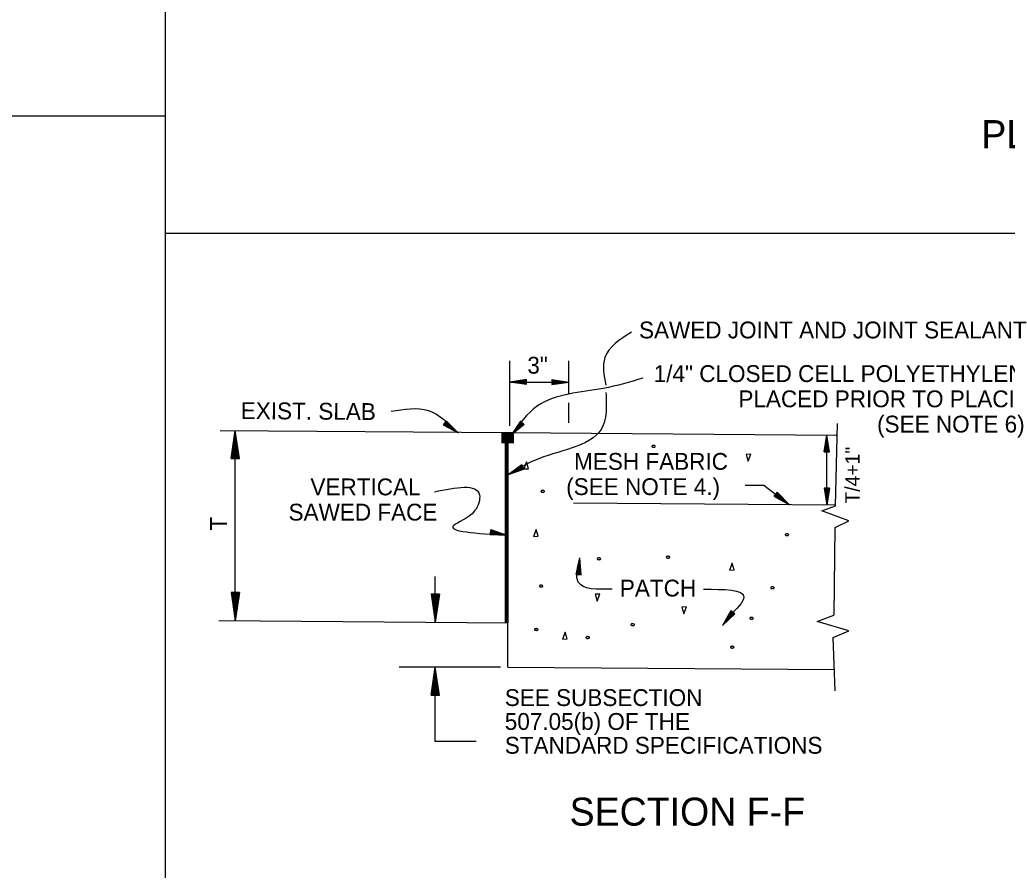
# Model space of a CAD drawing. Extents: x 1375738 to 1375905, y 380661 to 380875.
# Drawn here: x 1375781.94 to 1375810.09, y 380793.26 to 380817.52 of the extents above; entities that cross this region are included whole.
import ezdxf

# ---------------------------------------------------------------- set-up
doc = ezdxf.new("R2010")
doc.units = 0
doc.layers.add('R_Border', color=7, linetype='Continuous')
doc.layers.add('R_Draft', color=7, linetype='Continuous')

msp = doc.modelspace()

# ---------------------------------------------------------------- linework, layer by layer
at = {"layer": 'R_Border'}
for p, q in [((1375786.095, 380770.053), (1375786.095, 380850.32)), ((1375744.419, 380814.777), (1375786.095, 380814.777)), ((1375786.095, 380811.429), (1375854.78, 380811.429))]:
    msp.add_line(p, q, dxfattribs=at)
at = {"layer": 'R_Draft'}
for p, q in [((1375795.908, 380805.938), (1375795.908, 380807.788)), ((1375797.589, 380806.848), (1375797.589, 380807.788)), ((1375796.388, 380807.258), (1375795.908, 380807.186)), ((1375796.388, 380807.246), (1375795.988, 380807.186)), ((1375796.388, 380807.234), (1375796.071, 380807.186)), ((1375796.388, 380807.222), (1375796.151, 380807.186)), ((1375796.388, 380807.21), (1375796.232, 380807.186)), ((1375796.388, 380807.197), (1375796.312, 380807.186)), ((1375796.388, 380807.114), (1375796.388, 380807.258)), ((1375797.109, 380807.258), (1375797.589, 380807.186)), ((1375797.109, 380807.258), (1375797.109, 380807.114)), ((1375797.109, 380807.246), (1375797.509, 380807.186)), ((1375797.109, 380807.234), (1375797.426, 380807.186)), ((1375797.109, 380807.222), (1375797.346, 380807.186)), ((1375797.109, 380807.209), (1375797.265, 380807.186)), ((1375797.109, 380807.197), (1375797.185, 380807.186)), ((1375795.908, 380807.186), (1375797.589, 380807.186)), ((1375796.388, 380807.114), (1375795.908, 380807.186)), ((1375796.388, 380807.126), (1375795.988, 380807.186)), ((1375796.388, 380807.139), (1375796.071, 380807.186)), ((1375796.388, 380807.151), (1375796.151, 380807.186)), ((1375796.388, 380807.163), (1375796.232, 380807.186)), ((1375796.388, 380807.175), (1375796.312, 380807.186)), ((1375797.109, 380807.114), (1375797.589, 380807.186)), ((1375797.109, 380807.163), (1375797.265, 380807.186)), ((1375797.109, 380807.139), (1375797.426, 380807.186)), ((1375797.109, 380807.126), (1375797.509, 380807.186)), ((1375797.109, 380807.151), (1375797.346, 380807.186)), ((1375797.109, 380807.175), (1375797.185, 380807.186)), ((1375797.589, 380806.025), (1375797.589, 380806.597)), ((1375794.096, 380806.082), (1375794.008, 380805.967)), ((1375794.081, 380806.062), (1375794.305, 380805.833)), ((1375794.088, 380806.072), (1375794.37, 380805.783)), ((1375794.096, 380806.082), (1375794.434, 380805.734)), ((1375796.213, 380806.074), (1375795.945, 380805.669)), ((1375796.222, 380806.066), (1375795.999, 380805.729)), ((1375796.32, 380805.978), (1375796.213, 380806.074)), ((1375787.653, 380805.808), (1375795.908, 380805.745)), ((1375787.961, 380805.005), (1375788.081, 380805.805)), ((1375788.081, 380800.381), (1375788.081, 380805.805)), ((1375788.201, 380805.005), (1375788.081, 380805.805)), ((1375794.008, 380805.967), (1375794.434, 380805.734)), ((1375794.016, 380805.977), (1375794.37, 380805.783)), ((1375794.023, 380805.986), (1375794.305, 380805.833)), ((1375794.03, 380805.996), (1375794.241, 380805.881)), ((1375794.038, 380806.006), (1375794.176, 380805.93)), ((1375794.045, 380806.015), (1375794.112, 380805.979)), ((1375794.059, 380806.033), (1375794.112, 380805.979)), ((1375794.066, 380806.043), (1375794.176, 380805.93)), ((1375794.074, 380806.053), (1375794.241, 380805.881)), ((1375796.32, 380805.978), (1375795.945, 380805.669)), ((1375796.311, 380805.986), (1375795.999, 380805.729)), ((1375796.231, 380806.058), (1375796.054, 380805.79)), ((1375796.302, 380805.994), (1375796.054, 380805.79)), ((1375796.24, 380806.05), (1375796.108, 380805.849)), ((1375796.293, 380806.002), (1375796.108, 380805.849)), ((1375796.249, 380806.041), (1375796.162, 380805.91)), ((1375796.284, 380806.01), (1375796.162, 380805.91)), ((1375796.258, 380806.033), (1375796.216, 380805.969)), ((1375796.275, 380806.018), (1375796.216, 380805.969)), ((1375805.197, 380803.656), (1375805.25, 380806.003)), ((1375787.981, 380805.005), (1375788.081, 380805.671)), ((1375788.001, 380805.005), (1375788.081, 380805.534)), ((1375788.181, 380805.005), (1375788.081, 380805.671)), ((1375788.16, 380805.005), (1375788.081, 380805.534)), ((1375795.692, 380805.441), (1375795.694, 380805.759)), ((1375795.712, 380805.441), (1375795.714, 380805.759)), ((1375795.732, 380805.441), (1375795.734, 380805.758)), ((1375795.733, 380805.441), (1375795.736, 380805.758)), ((1375795.752, 380805.441), (1375795.754, 380805.758)), ((1375795.772, 380805.441), (1375795.774, 380805.758)), ((1375795.786, 380800.321), (1375795.786, 380805.745)), ((1375795.792, 380805.441), (1375795.794, 380805.758)), ((1375795.806, 380800.321), (1375795.806, 380805.745)), ((1375795.809, 380800.321), (1375795.809, 380805.745)), ((1375795.812, 380805.441), (1375795.814, 380805.758)), ((1375795.826, 380800.321), (1375795.826, 380805.745)), ((1375795.832, 380805.44), (1375795.834, 380805.757)), ((1375795.846, 380800.321), (1375795.846, 380805.745)), ((1375795.852, 380805.44), (1375795.854, 380805.757)), ((1375795.856, 380799.057), (1375795.856, 380805.745)), ((1375795.866, 380800.321), (1375795.866, 380805.745)), ((1375795.872, 380805.44), (1375795.874, 380805.757)), ((1375795.892, 380805.44), (1375795.894, 380805.757)), ((1375795.908, 380805.745), (1375805.218, 380805.673)), ((1375795.912, 380805.44), (1375795.914, 380805.757)), ((1375795.932, 380805.44), (1375795.934, 380805.757)), ((1375795.952, 380805.439), (1375795.954, 380805.757)), ((1375795.972, 380805.439), (1375795.974, 380805.757)), ((1375795.992, 380805.439), (1375795.994, 380805.756)), ((1375796.012, 380805.439), (1375796.014, 380805.756)), ((1375804.877, 380805.195), (1375804.949, 380805.675)), ((1375804.889, 380805.195), (1375804.949, 380805.595)), ((1375804.901, 380805.195), (1375804.949, 380805.512)), ((1375804.949, 380803.677), (1375804.949, 380805.675)), ((1375805.021, 380805.195), (1375804.949, 380805.675)), ((1375805.009, 380805.195), (1375804.949, 380805.595)), ((1375804.997, 380805.195), (1375804.949, 380805.512)), ((1375788.021, 380805.005), (1375788.081, 380805.401)), ((1375788.042, 380805.005), (1375788.081, 380805.265)), ((1375788.14, 380805.005), (1375788.081, 380805.401)), ((1375788.12, 380805.005), (1375788.081, 380805.265)), ((1375804.913, 380805.195), (1375804.949, 380805.432)), ((1375804.926, 380805.195), (1375804.949, 380805.351)), ((1375804.938, 380805.195), (1375804.949, 380805.271)), ((1375804.985, 380805.195), (1375804.949, 380805.432)), ((1375804.973, 380805.195), (1375804.949, 380805.351)), ((1375804.96, 380805.195), (1375804.949, 380805.271)), ((1375787.961, 380805.005), (1375788.201, 380805.005)), ((1375788.062, 380805.005), (1375788.081, 380805.131)), ((1375788.1, 380805.005), (1375788.081, 380805.131)), ((1375804.877, 380805.195), (1375805.021, 380805.195)), ((1375796.254, 380804.828), (1375795.862, 380804.541)), ((1375796.32, 380804.7), (1375795.862, 380804.541)), ((1375796.259, 380804.817), (1375795.933, 380804.579)), ((1375796.315, 380804.711), (1375795.933, 380804.579)), ((1375796.265, 380804.807), (1375796.006, 380804.617)), ((1375796.309, 380804.722), (1375796.006, 380804.617)), ((1375796.27, 380804.796), (1375796.076, 380804.654)), ((1375796.304, 380804.733), (1375796.076, 380804.654)), ((1375796.276, 380804.785), (1375796.149, 380804.692)), ((1375796.298, 380804.743), (1375796.149, 380804.692)), ((1375796.282, 380804.774), (1375796.22, 380804.729)), ((1375796.292, 380804.754), (1375796.22, 380804.729)), ((1375796.32, 380804.7), (1375796.254, 380804.828)), ((1375802.616, 380804.244), (1375803.151, 380804.244)), ((1375803.151, 380804.244), (1375803.881, 380803.686)), ((1375804.877, 380804.157), (1375804.949, 380803.677)), ((1375805.021, 380804.157), (1375804.877, 380804.157)), ((1375804.889, 380804.157), (1375804.949, 380803.757)), ((1375804.901, 380804.157), (1375804.949, 380803.84)), ((1375804.913, 380804.157), (1375804.949, 380803.92)), ((1375804.925, 380804.157), (1375804.949, 380804.001)), ((1375804.938, 380804.157), (1375804.949, 380804.081)), ((1375805.021, 380804.157), (1375804.949, 380803.677)), ((1375804.972, 380804.157), (1375804.949, 380804.001)), ((1375804.997, 380804.157), (1375804.949, 380803.84)), ((1375805.009, 380804.157), (1375804.949, 380803.757)), ((1375804.985, 380804.157), (1375804.949, 380803.92)), ((1375804.96, 380804.157), (1375804.949, 380804.081)), ((1375803.529, 380804.049), (1375803.438, 380803.93)), ((1375803.438, 380803.93), (1375803.881, 380803.686)), ((1375803.446, 380803.94), (1375803.815, 380803.736)), ((1375803.454, 380803.95), (1375803.746, 380803.789)), ((1375803.461, 380803.96), (1375803.68, 380803.839)), ((1375803.469, 380803.97), (1375803.613, 380803.891)), ((1375803.477, 380803.98), (1375803.547, 380803.942)), ((1375803.491, 380803.999), (1375803.547, 380803.942)), ((1375803.499, 380804.009), (1375803.613, 380803.891)), ((1375803.507, 380804.019), (1375803.68, 380803.839)), ((1375803.514, 380804.029), (1375803.746, 380803.789)), ((1375803.522, 380804.039), (1375803.815, 380803.736)), ((1375803.529, 380804.049), (1375803.881, 380803.686)), ((1375805.198, 380803.675), (1375797.721, 380803.733)), ((1375804.81, 380803.516), (1375805.197, 380803.656)), ((1375805.574, 380803.228), (1375804.81, 380803.516)), ((1375795.364, 380802.979), (1375795.338, 380802.837)), ((1375795.362, 380802.967), (1375795.744, 380802.837)), ((1375795.364, 380802.979), (1375795.823, 380802.822)), ((1375805.154, 380800.539), (1375805.183, 380803.04)), ((1375805.183, 380803.04), (1375805.574, 380803.228)), ((1375795.338, 380802.837), (1375795.823, 380802.822)), ((1375795.34, 380802.849), (1375795.744, 380802.837)), ((1375795.342, 380802.861), (1375795.663, 380802.851)), ((1375795.344, 380802.873), (1375795.584, 380802.866)), ((1375795.347, 380802.885), (1375795.504, 380802.88)), ((1375795.349, 380802.897), (1375795.426, 380802.895)), ((1375795.353, 380802.919), (1375795.426, 380802.895)), ((1375795.355, 380802.931), (1375795.504, 380802.88)), ((1375795.357, 380802.943), (1375795.584, 380802.866)), ((1375795.36, 380802.955), (1375795.663, 380802.851)), ((1375797.804, 380801.695), (1375797.908, 380802.169)), ((1375797.947, 380801.686), (1375797.908, 380802.169)), ((1375797.816, 380801.695), (1375797.903, 380802.09)), ((1375797.828, 380801.694), (1375797.897, 380802.007)), ((1375797.84, 380801.693), (1375797.892, 380801.928)), ((1375797.853, 380801.692), (1375797.886, 380801.846)), ((1375797.899, 380801.689), (1375797.886, 380801.846)), ((1375797.912, 380801.688), (1375797.892, 380801.928)), ((1375797.924, 380801.688), (1375797.897, 380802.007)), ((1375797.936, 380801.687), (1375797.903, 380802.09)), ((1375793.784, 380800.337), (1375793.784, 380801.644)), ((1375797.804, 380801.695), (1375797.947, 380801.686)), ((1375797.864, 380801.692), (1375797.881, 380801.767)), ((1375797.887, 380801.69), (1375797.881, 380801.767)), ((1375787.961, 380801.181), (1375788.081, 380800.381)), ((1375788.201, 380801.181), (1375787.961, 380801.181)), ((1375787.981, 380801.181), (1375788.081, 380800.515)), ((1375788.001, 380801.181), (1375788.081, 380800.652)), ((1375788.021, 380801.181), (1375788.081, 380800.785)), ((1375788.042, 380801.181), (1375788.081, 380800.921)), ((1375788.062, 380801.181), (1375788.081, 380801.055)), ((1375788.201, 380801.181), (1375788.081, 380800.381)), ((1375788.12, 380801.181), (1375788.081, 380800.921)), ((1375788.16, 380801.181), (1375788.081, 380800.652)), ((1375788.181, 380801.181), (1375788.081, 380800.515)), ((1375788.14, 380801.181), (1375788.081, 380800.785)), ((1375788.1, 380801.181), (1375788.081, 380801.055)), ((1375793.664, 380801.137), (1375793.784, 380800.337)), ((1375793.904, 380801.137), (1375793.664, 380801.137)), ((1375793.684, 380801.137), (1375793.784, 380800.471)), ((1375793.705, 380801.137), (1375793.784, 380800.608)), ((1375793.725, 380801.137), (1375793.784, 380800.741)), ((1375793.745, 380801.137), (1375793.784, 380800.877)), ((1375793.766, 380801.137), (1375793.784, 380801.011)), ((1375793.904, 380801.137), (1375793.784, 380800.337)), ((1375793.823, 380801.137), (1375793.784, 380800.877)), ((1375793.864, 380801.137), (1375793.784, 380800.608)), ((1375793.884, 380801.137), (1375793.784, 380800.471)), ((1375793.844, 380801.137), (1375793.784, 380800.741)), ((1375793.803, 380801.137), (1375793.784, 380801.011)), ((1375802.208, 380800.664), (1375801.974, 380800.239)), ((1375802.323, 380800.577), (1375801.974, 380800.239)), ((1375802.218, 380800.657), (1375802.023, 380800.303)), ((1375802.313, 380800.584), (1375802.023, 380800.303)), ((1375802.228, 380800.649), (1375802.073, 380800.368)), ((1375802.304, 380800.591), (1375802.073, 380800.368)), ((1375802.237, 380800.642), (1375802.121, 380800.432)), ((1375802.294, 380800.599), (1375802.121, 380800.432)), ((1375802.247, 380800.635), (1375802.171, 380800.496)), ((1375802.284, 380800.606), (1375802.171, 380800.496)), ((1375802.323, 380800.577), (1375802.208, 380800.664)), ((1375802.257, 380800.627), (1375802.22, 380800.56)), ((1375802.274, 380800.613), (1375802.22, 380800.56)), ((1375804.676, 380800.361), (1375805.147, 380800.536)), ((1375787.612, 380800.385), (1375795.866, 380800.321)), ((1375805.58, 380800.088), (1375804.676, 380800.361)), ((1375805.133, 380799.904), (1375805.58, 380800.088)), ((1375805.189, 380798.378), (1375805.133, 380799.904)), ((1375795.64, 380799.057), (1375792.753, 380799.057)), ((1375793.664, 380798.257), (1375793.784, 380799.057)), ((1375793.904, 380798.257), (1375793.784, 380799.057)), ((1375793.784, 380796.935), (1375793.784, 380799.057)), ((1375795.856, 380799.057), (1375805.166, 380798.985)), ((1375793.684, 380798.257), (1375793.784, 380798.923)), ((1375793.705, 380798.257), (1375793.784, 380798.786)), ((1375793.884, 380798.257), (1375793.784, 380798.923)), ((1375793.864, 380798.257), (1375793.784, 380798.786)), ((1375793.725, 380798.257), (1375793.784, 380798.653)), ((1375793.746, 380798.257), (1375793.784, 380798.517)), ((1375793.844, 380798.257), (1375793.784, 380798.653)), ((1375793.824, 380798.257), (1375793.784, 380798.517)), ((1375793.664, 380798.257), (1375793.904, 380798.257)), ((1375793.766, 380798.257), (1375793.784, 380798.383)), ((1375793.803, 380798.257), (1375793.784, 380798.383)), ((1375794.947, 380796.935), (1375793.784, 380796.935))]:
    msp.add_line(p, q, dxfattribs=at)
for points in [[(1375802.705, 380804.927), (1375802.778, 380805.126), (1375802.646, 380805.121), (1375802.705, 380804.927)], [(1375796.385, 380804.909), (1375796.312, 380804.71), (1375796.445, 380804.715), (1375796.385, 380804.909)], [(1375796.66, 380802.985), (1375796.588, 380802.786), (1375796.72, 380802.791), (1375796.66, 380802.985)], [(1375802.25, 380802.023), (1375802.177, 380801.823), (1375802.309, 380801.829), (1375802.25, 380802.023)], [(1375798.399, 380800.941), (1375798.472, 380801.14), (1375798.339, 380801.135), (1375798.399, 380800.941)], [(1375800.873, 380800.574), (1375800.946, 380800.774), (1375800.813, 380800.768), (1375800.873, 380800.574)], [(1375797.485, 380800.053), (1375797.412, 380799.853), (1375797.544, 380799.859), (1375797.485, 380800.053)]]:
    msp.add_lwpolyline(points, dxfattribs=at)
for points in [[(1375799.378, 380808.612), (1375798.618, 380807.882), (1375798.643, 380807.101)], [(1375799.703, 380807.297), (1375798.576, 380807.005), (1375796.697, 380806.504), (1375795.945, 380805.669)], [(1375798.65, 380806.89), (1375798.66, 380806.587), (1375798.576, 380805.961), (1375796.738, 380805.001), (1375795.862, 380804.541)], [(1375792.525, 380806.352), (1375793.59, 380806.375), (1375794.434, 380805.734)], [(1375800.009, 380805.377), (1375800.026, 380805.375), (1375800.047, 380805.368), (1375800.057, 380805.358), (1375800.059, 380805.352), (1375800.053, 380805.341), (1375800.047, 380805.337), (1375800.035, 380805.331), (1375800.018, 380805.327), (1375800.009, 380805.327), (1375799.996, 380805.329), (1375799.981, 380805.331), (1375799.97, 380805.336), (1375799.96, 380805.345), (1375799.959, 380805.352), (1375799.962, 380805.362), (1375799.97, 380805.368), (1375799.978, 380805.372), (1375799.99, 380805.375), (1375799.998, 380805.377), (1375800.009, 380805.377)], [(1375793.762, 380804.059), (1375795.044, 380803.968), (1375794.907, 380803.509), (1375794.312, 380803.097), (1375795.823, 380802.822)], [(1375796.848, 380804.095), (1375796.865, 380804.093), (1375796.886, 380804.085), (1375796.896, 380804.075), (1375796.898, 380804.069), (1375796.892, 380804.059), (1375796.886, 380804.054), (1375796.874, 380804.048), (1375796.856, 380804.045), (1375796.848, 380804.045), (1375796.834, 380804.046), (1375796.82, 380804.048), (1375796.809, 380804.053), (1375796.799, 380804.063), (1375796.798, 380804.069), (1375796.801, 380804.079), (1375796.809, 380804.085), (1375796.817, 380804.089), (1375796.829, 380804.093), (1375796.836, 380804.094), (1375796.848, 380804.095)], [(1375803.811, 380802.858), (1375803.829, 380802.856), (1375803.849, 380802.849), (1375803.86, 380802.839), (1375803.861, 380802.833), (1375803.856, 380802.822), (1375803.85, 380802.817), (1375803.837, 380802.811), (1375803.82, 380802.808), (1375803.811, 380802.808), (1375803.798, 380802.809), (1375803.784, 380802.811), (1375803.773, 380802.817), (1375803.763, 380802.826), (1375803.761, 380802.833), (1375803.764, 380802.842), (1375803.772, 380802.849), (1375803.78, 380802.852), (1375803.792, 380802.856), (1375803.8, 380802.857), (1375803.811, 380802.858)], [(1375798.832, 380801.279), (1375797.862, 380801.482), (1375797.908, 380802.169)], [(1375798.451, 380802.171), (1375798.469, 380802.169), (1375798.489, 380802.161), (1375798.5, 380802.151), (1375798.501, 380802.145), (1375798.496, 380802.135), (1375798.49, 380802.13), (1375798.477, 380802.124), (1375798.46, 380802.121), (1375798.451, 380802.121), (1375798.438, 380802.122), (1375798.424, 380802.124), (1375798.413, 380802.129), (1375798.403, 380802.139), (1375798.401, 380802.145), (1375798.404, 380802.155), (1375798.412, 380802.161), (1375798.42, 380802.165), (1375798.432, 380802.169), (1375798.44, 380802.17), (1375798.451, 380802.171)], [(1375800.421, 380802.217), (1375800.439, 380802.215), (1375800.459, 380802.207), (1375800.47, 380802.197), (1375800.471, 380802.191), (1375800.466, 380802.181), (1375800.46, 380802.176), (1375800.447, 380802.17), (1375800.43, 380802.167), (1375800.421, 380802.167), (1375800.408, 380802.168), (1375800.394, 380802.17), (1375800.383, 380802.175), (1375800.373, 380802.185), (1375800.371, 380802.191), (1375800.374, 380802.201), (1375800.382, 380802.207), (1375800.39, 380802.211), (1375800.402, 380802.215), (1375800.41, 380802.216), (1375800.421, 380802.217)], [(1375796.802, 380801.392), (1375796.819, 380801.39), (1375796.84, 380801.383), (1375796.85, 380801.373), (1375796.852, 380801.367), (1375796.846, 380801.356), (1375796.84, 380801.351), (1375796.828, 380801.345), (1375796.81, 380801.342), (1375796.802, 380801.342), (1375796.788, 380801.343), (1375796.774, 380801.345), (1375796.763, 380801.351), (1375796.753, 380801.36), (1375796.752, 380801.367), (1375796.755, 380801.376), (1375796.763, 380801.383), (1375796.771, 380801.386), (1375796.783, 380801.39), (1375796.79, 380801.391), (1375796.802, 380801.392)], [(1375801.434, 380801.279), (1375802.584, 380801.054), (1375802.155, 380800.493)], [(1375803.399, 380801.346), (1375803.416, 380801.344), (1375803.437, 380801.337), (1375803.447, 380801.327), (1375803.449, 380801.321), (1375803.443, 380801.31), (1375803.437, 380801.305), (1375803.425, 380801.299), (1375803.408, 380801.296), (1375803.399, 380801.296), (1375803.386, 380801.297), (1375803.371, 380801.299), (1375803.36, 380801.305), (1375803.35, 380801.314), (1375803.349, 380801.321), (1375803.352, 380801.33), (1375803.36, 380801.337), (1375803.368, 380801.34), (1375803.38, 380801.344), (1375803.388, 380801.345), (1375803.399, 380801.346)], [(1375802.803, 380800.475), (1375802.821, 380800.473), (1375802.841, 380800.466), (1375802.852, 380800.456), (1375802.853, 380800.45), (1375802.848, 380800.439), (1375802.842, 380800.435), (1375802.829, 380800.429), (1375802.812, 380800.425), (1375802.803, 380800.425), (1375802.79, 380800.427), (1375802.776, 380800.429), (1375802.765, 380800.434), (1375802.755, 380800.443), (1375802.753, 380800.45), (1375802.756, 380800.46), (1375802.764, 380800.466), (1375802.772, 380800.47), (1375802.784, 380800.473), (1375802.792, 380800.475), (1375802.803, 380800.475)], [(1375796.664, 380800.155), (1375796.682, 380800.153), (1375796.702, 380800.146), (1375796.713, 380800.136), (1375796.714, 380800.13), (1375796.709, 380800.119), (1375796.703, 380800.114), (1375796.69, 380800.109), (1375796.673, 380800.105), (1375796.664, 380800.105), (1375796.651, 380800.106), (1375796.637, 380800.109), (1375796.626, 380800.114), (1375796.616, 380800.123), (1375796.614, 380800.13), (1375796.618, 380800.139), (1375796.626, 380800.146), (1375796.634, 380800.149), (1375796.646, 380800.153), (1375796.653, 380800.155), (1375796.664, 380800.155)], [(1375799.413, 380800.292), (1375799.431, 380800.29), (1375799.451, 380800.283), (1375799.462, 380800.273), (1375799.463, 380800.267), (1375799.458, 380800.256), (1375799.452, 380800.251), (1375799.439, 380800.246), (1375799.422, 380800.242), (1375799.413, 380800.242), (1375799.4, 380800.243), (1375799.386, 380800.246), (1375799.375, 380800.251), (1375799.365, 380800.26), (1375799.363, 380800.267), (1375799.366, 380800.277), (1375799.374, 380800.283), (1375799.382, 380800.287), (1375799.394, 380800.29), (1375799.402, 380800.292), (1375799.413, 380800.292)], [(1375798.13, 380799.926), (1375798.148, 380799.924), (1375798.168, 380799.917), (1375798.179, 380799.907), (1375798.18, 380799.901), (1375798.175, 380799.89), (1375798.169, 380799.885), (1375798.156, 380799.879), (1375798.139, 380799.876), (1375798.13, 380799.876), (1375798.117, 380799.877), (1375798.103, 380799.879), (1375798.092, 380799.885), (1375798.082, 380799.894), (1375798.08, 380799.901), (1375798.084, 380799.91), (1375798.092, 380799.917), (1375798.1, 380799.92), (1375798.112, 380799.924), (1375798.119, 380799.925), (1375798.13, 380799.926)], [(1375802.254, 380799.651), (1375802.271, 380799.649), (1375802.292, 380799.642), (1375802.302, 380799.632), (1375802.304, 380799.626), (1375802.298, 380799.615), (1375802.292, 380799.61), (1375802.28, 380799.605), (1375802.262, 380799.601), (1375802.254, 380799.601), (1375802.24, 380799.602), (1375802.226, 380799.605), (1375802.215, 380799.61), (1375802.205, 380799.619), (1375802.204, 380799.626), (1375802.207, 380799.635), (1375802.215, 380799.642), (1375802.223, 380799.645), (1375802.235, 380799.649), (1375802.242, 380799.651), (1375802.254, 380799.651)]]:
    msp.add_spline(points, degree=3, dxfattribs=at)

# ---------------------------------------------------------------- texts
for s, height, p in [('PLAN OF PAVEMENT REPAIR', 0.8, (1375809.354, 380813.855)), ('SAWED JOINT AND JOINT SEALANT', 0.48, (1375799.594, 380808.431)), ('3"', 0.48, (1375796.409, 380807.426)), ('1/4" CLOSED CELL POLYETHYLENE FOAM TO BE', 0.48, (1375800.013, 380807.187)), ('PLACED PRIOR TO PLACING PATCH.', 0.48, (1375802.428, 380806.467)), ('(SEE NOTE 6)', 0.48, (1375806.382, 380805.747)), ('MESH FABRIC', 0.48, (1375797.743, 380804.683)), ('VERTICAL', 0.48, (1375790.225, 380803.956)), ('(SEE NOTE 4.)', 0.48, (1375797.518, 380803.963)), ('SAWED FACE', 0.48, (1375789.601, 380803.236)), ('PATCH', 0.48, (1375799.048, 380801.07)), ('SEE SUBSECTION', 0.48, (1375795.766, 380797.947)), ('507.05(b) OF THE', 0.48, (1375795.766, 380797.267)), ('STANDARD SPECIFICATIONS', 0.48, (1375795.766, 380796.587)), ('SECTION F-F', 0.7996, (1375797.615, 380794.536))]:
    msp.add_text(s, height=height, dxfattribs=at).set_placement(p)
for s, height, rotation, p in [('EXIST. SLAB', 0.47999, 359.5586, (1375788.236, 380806.132)), ('T/4+1"', 0.4116, 90, (1375805.885, 380803.722)), ('T', 0.48, 90, (1375787.841, 380802.952))]:
    msp.add_text(s, height=height, rotation=rotation, dxfattribs=at).set_placement(p)

doc.saveas('drawing.dxf')
